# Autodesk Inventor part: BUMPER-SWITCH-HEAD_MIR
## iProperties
Created: 2007-08
Part Number: BUMPER-SWITCH-HEAD_MIR
Material: ABS Plastic
Document SubType Name: Modeling
Density: 1.06 g/cm^3
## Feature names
1. Derived Body1 [Tagging]
